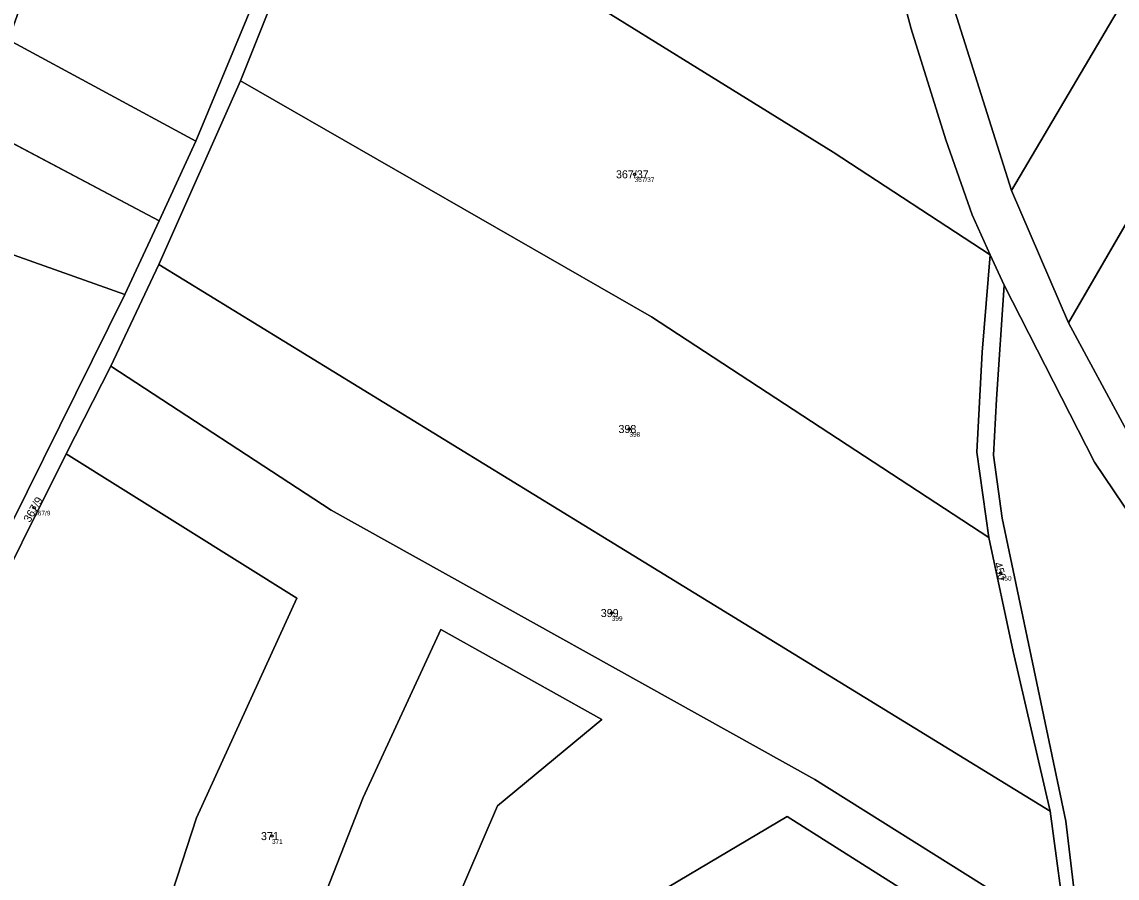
# Model space of a CAD drawing. Extents: x -700238 to -698499, y -1070626 to -1068006.
# Drawn here: x -699982.4 to -699749.9, y -1070051.8 to -1069869.9 of the extents above; entities that cross this region are included whole.
import ezdxf

# ---------------------------------------------------------------- set-up
doc = ezdxf.new("R2010")
doc.units = 0
for name, color, linetype in [('Definiční body', 7, 'Continuous'), ('Hranice parcel', 7, 'Continuous'), ('Parcelní čísla', 7, 'Continuous'), ('Polygon parcely', 7, 'Continuous')]:
    doc.layers.add(name, color=color, linetype=linetype)

msp = doc.modelspace()

# ---------------------------------------------------------------- linework, layer by layer
at = {"layer": 'Definiční body'}
for centre in [(-699852.34, -1069902.28994), (-699853.43, -1069956.39994), (-699979.84, -1069973.10994), (-699774.58, -1069986.95994), (-699857.19, -1069995.49994), (-699929.35, -1070042.87994)]:
    msp.add_circle(centre, 0.25, dxfattribs=at)
at = {"layer": 'Hranice parcel'}
for p, q in [((-699666.52, -1069772.25), (-699760.19, -1069933.83)), ((-699786.04, -1069862.19), (-699772.32, -1069905.7)), ((-699953.29, -1069912.16), (-700026.88, -1069873.22)), ((-699953.34, -1069921.42), (-699936.01, -1069882.46)), ((-699945.5, -1069895.24), (-699953.29, -1069912.16)), ((-699760.19, -1069933.83), (-699772.32, -1069905.7)), ((-699953.29, -1069912.16), (-699960.55, -1069927.82)), ((-699776.82, -1069919.37), (-699773.88, -1069925.87)), ((-699963.55, -1069943.05), (-699953.34, -1069921.42)), ((-699747.8, -1069956.79), (-699760.19, -1069933.83)), ((-699973.03, -1069961.64), (-699963.55, -1069943.05)), ((-699760.48, -1070064.46), (-699764.05, -1070037.6))]:
    msp.add_line(p, q, dxfattribs=at)
for points in [[(-699772.32, -1069905.7), (-699718.65, -1069814.76), (-699688.94, -1069762.18)], [(-699934.67, -1069766.79), (-699943.48, -1069779.63), (-699961.27, -1069826.27), (-699966.61, -1069825.7), (-699975.69, -1069846.7), (-699985.26, -1069873.71), (-699945.5, -1069895.24)], [(-699899.18, -1069805.87), (-699908.38, -1069815.7), (-699910.51, -1069819.6), (-699923.83, -1069843.06), (-699945.5, -1069895.24)], [(-699936.01, -1069882.46), (-699921.26, -1069845.41), (-699917.53, -1069838.96)], [(-699776.82, -1069919.37), (-699810.15, -1069897.58), (-699890.66, -1069847.63)], [(-699795.87, -1069862.82), (-699793.62, -1069871.36), (-699786.24, -1069895), (-699780.65, -1069910.87), (-699776.82, -1069919.37)], [(-699936.01, -1069882.46), (-699848.76, -1069932.55), (-699777.09, -1069979.45)], [(-699960.55, -1069927.82), (-700000.29, -1069913.75), (-700035.34, -1069906.98)], [(-699777.09, -1069979.45), (-699779.64, -1069961.35), (-699778.54, -1069940.11), (-699776.82, -1069919.37)], [(-699953.34, -1069921.42), (-699857.82, -1069980.05), (-699764.05, -1070037.6)], [(-699773.88, -1069925.87), (-699775.47, -1069950.06), (-699776.09, -1069961.97), (-699774.25, -1069975.35), (-699760.75, -1070039.69), (-699757.63, -1070065.88), (-699760.48, -1070064.46)], [(-699773.88, -1069925.87), (-699754.67, -1069963.44), (-699736.31, -1069990.62)], [(-699960.55, -1069927.82), (-699984.81, -1069976.77), (-700014.15, -1070035.06), (-700028.52, -1070073.11), (-700029.38, -1070092.64)], [(-699760.48, -1070064.46), (-699814.07, -1070030.89), (-699916.79, -1069973.61), (-699963.55, -1069943.05)], [(-700022.52, -1070128.11), (-700025.92, -1070097.31), (-700025.83, -1070074.31), (-700010.65, -1070036.99), (-699973.03, -1069961.64)], [(-699854.27, -1070196.19), (-699869.64, -1070194.62), (-699892.83, -1070188.84), (-699913.08, -1070162.82), (-699928.47, -1070131.78), (-699793.52, -1070055.46), (-699819.94, -1070038.73), (-699903.8, -1070088.48), (-699881.47, -1070036.48), (-699859.27, -1070018.12), (-699893.51, -1069998.97), (-699909.95, -1070034.69), (-699926.64, -1070077.05), (-699936.46, -1070111.92), (-699945.42, -1070093.75), (-699957.78, -1070077.02), (-699945.33, -1070038.99), (-699924.07, -1069992.37), (-699973.03, -1069961.64)], [(-699764.05, -1070037.6), (-699771.94, -1070003.65), (-699777.09, -1069979.45)]]:
    msp.add_lwpolyline(points, dxfattribs=at)
at = {"layer": 'Polygon parcely'}
for points in [[(-699666.31, -1070068.88), (-699678.79, -1070051.48), (-699693.87, -1070032.39), (-699718.55, -1069997.74), (-699733.13, -1069977.54), (-699747.8, -1069956.79), (-699760.19, -1069933.83), (-699772.32, -1069905.7), (-699786.04, -1069862.19), (-699789.84, -1069849.05), (-699797.44, -1069825.52), (-699807.14, -1069798.04), (-699808.65, -1069790.69), (-699809.76, -1069785.77), (-699810.32, -1069782.64), (-699811.1, -1069770), (-699809.25, -1069756.98), (-699803.18, -1069743.13), (-699792.05, -1069721.6), (-699779, -1069695.71)], [(-699820.65, -1069756.64), (-699822.8, -1069770.73), (-699819.03, -1069786.16), (-699815.5, -1069803.39), (-699809.91, -1069821.04), (-699795.87, -1069862.82), (-699793.62, -1069871.36), (-699786.24, -1069895), (-699780.65, -1069910.87), (-699776.82, -1069919.37), (-699773.88, -1069925.87), (-699754.67, -1069963.44), (-699736.31, -1069990.62), (-699727.1, -1070003.14), (-699698.54, -1070041.6), (-699662.16, -1070090.9)], [(-700025.83, -1070074.31), (-700010.65, -1070036.99), (-699973.03, -1069961.64), (-699963.55, -1069943.05), (-699953.34, -1069921.42), (-699936.01, -1069882.46), (-699921.26, -1069845.41), (-699917.53, -1069838.96), (-699918.26, -1069838.61), (-699908.41, -1069817.82), (-699905.55, -1069819.19), (-699899.18, -1069805.87), (-699908.38, -1069815.7), (-699910.51, -1069819.6), (-699923.83, -1069843.06), (-699945.5, -1069895.24), (-699953.29, -1069912.16), (-699960.55, -1069927.82), (-699984.81, -1069976.77), (-700014.15, -1070035.06), (-700028.52, -1070073.11)], [(-699723.72, -1070090.01), (-699733.66, -1070045.81), (-699736.31, -1069990.62), (-699754.67, -1069963.44), (-699773.88, -1069925.87), (-699775.47, -1069950.06), (-699776.09, -1069961.97), (-699774.25, -1069975.35), (-699760.75, -1070039.69), (-699757.63, -1070065.88)], [(-699760.48, -1070064.46), (-699814.07, -1070030.89), (-699916.79, -1069973.61), (-699963.55, -1069943.05), (-699973.03, -1069961.64), (-699924.07, -1069992.37), (-699945.33, -1070038.99), (-699957.78, -1070077.02)], [(-699957.78, -1070077.02), (-699945.33, -1070038.99), (-699924.07, -1069992.37), (-699973.03, -1069961.64), (-700010.65, -1070036.99), (-700025.83, -1070074.31)], [(-699793.52, -1070055.46), (-699819.94, -1070038.73), (-699903.8, -1070088.48), (-699881.47, -1070036.48), (-699859.27, -1070018.12), (-699893.51, -1069998.97), (-699909.95, -1070034.69), (-699926.64, -1070077.05)], [(-699926.64, -1070077.05), (-699909.95, -1070034.69), (-699893.51, -1069998.97), (-699859.27, -1070018.12), (-699881.47, -1070036.48), (-699903.8, -1070088.48), (-699819.94, -1070038.73), (-699793.52, -1070055.46)]]:
    msp.add_lwpolyline(points, dxfattribs=at)
for points in [[(-700026.88, -1069873.22), (-699953.29, -1069912.16), (-699945.5, -1069895.24), (-699985.26, -1069873.71), (-699975.69, -1069846.7), (-699966.61, -1069825.7), (-699961.27, -1069826.27), (-699943.48, -1069779.63), (-699934.67, -1069766.79), (-699980.93, -1069741.29), (-699999.19, -1069781.82), (-700020, -1069850.14)], [(-699718.65, -1069814.76), (-699688.94, -1069762.18), (-699710.07, -1069755.22), (-699786.04, -1069862.19), (-699772.32, -1069905.7)], [(-699772.32, -1069905.7), (-699760.19, -1069933.83), (-699666.52, -1069772.25), (-699688.94, -1069762.18), (-699718.65, -1069814.76)], [(-699985.26, -1069873.71), (-699945.5, -1069895.24), (-699923.83, -1069843.06), (-699910.51, -1069819.6), (-699908.38, -1069815.7), (-699899.18, -1069805.87), (-699891.37, -1069789.56), (-699915.87, -1069777), (-699934.67, -1069766.79), (-699943.48, -1069779.63), (-699961.27, -1069826.27), (-699966.61, -1069825.7), (-699975.69, -1069846.7)], [(-699666.52, -1069772.25), (-699760.19, -1069933.83), (-699747.8, -1069956.79), (-699670.62, -1069815.86), (-699648.85, -1069777.23)], [(-699795.87, -1069862.82), (-699877.25, -1069814.06), (-699887.28, -1069835.16), (-699886.33, -1069835.61), (-699887.34, -1069837.73), (-699886.21, -1069838.27), (-699890.66, -1069847.63), (-699810.15, -1069897.58), (-699776.82, -1069919.37), (-699780.65, -1069910.87), (-699786.24, -1069895), (-699793.62, -1069871.36)], [(-699890.66, -1069847.63), (-699892.24, -1069850.96), (-699897.84, -1069848.3), (-699901.7, -1069856.43), (-699915.43, -1069849.92), (-699911.57, -1069841.79), (-699917.53, -1069838.96), (-699921.26, -1069845.41), (-699936.01, -1069882.46), (-699848.76, -1069932.55), (-699777.09, -1069979.45), (-699779.64, -1069961.35), (-699778.54, -1069940.11), (-699776.82, -1069919.37), (-699810.15, -1069897.58)], [(-700026.88, -1069873.22), (-700031.54, -1069887.09), (-700035.34, -1069906.98), (-700000.29, -1069913.75), (-699960.55, -1069927.82), (-699953.29, -1069912.16)], [(-699953.34, -1069921.42), (-699857.82, -1069980.05), (-699764.05, -1070037.6), (-699771.94, -1070003.65), (-699777.09, -1069979.45), (-699848.76, -1069932.55), (-699936.01, -1069882.46)], [(-699960.55, -1069927.82), (-700000.29, -1069913.75), (-700035.34, -1069906.98), (-700040.48, -1069934.75), (-700041.71, -1069955.38), (-700048.46, -1069970.6), (-700048.21, -1069994.79), (-700039.13, -1070061.09), (-700032.26, -1070092.89), (-700029.38, -1070092.64), (-700028.52, -1070073.11), (-700014.15, -1070035.06), (-699984.81, -1069976.77)], [(-699776.82, -1069919.37), (-699778.54, -1069940.11), (-699779.64, -1069961.35), (-699777.09, -1069979.45), (-699771.94, -1070003.65), (-699764.05, -1070037.6), (-699760.48, -1070064.46), (-699757.63, -1070065.88), (-699760.75, -1070039.69), (-699774.25, -1069975.35), (-699776.09, -1069961.97), (-699775.47, -1069950.06), (-699773.88, -1069925.87)], [(-699764.05, -1070037.6), (-699857.82, -1069980.05), (-699953.34, -1069921.42), (-699963.55, -1069943.05), (-699916.79, -1069973.61), (-699814.07, -1070030.89), (-699760.48, -1070064.46)]]:
    msp.add_lwpolyline(points, close=True, dxfattribs=at)

# ---------------------------------------------------------------- texts
at = {"layer": 'Definiční body'}
for s, p in [('367/37', (-699852.34, -1069903.946)), ('398', (-699853.43, -1069958.056)), ('367/9', (-699979.84, -1069974.766)), ('450', (-699774.58, -1069988.616)), ('399', (-699857.19, -1069997.156)), ('371', (-699929.35, -1070044.536))]:
    msp.add_text(s, height=0.999996, dxfattribs=at).set_placement(p)
at = {"layer": 'Parcelní čísla'}
for s, p in [('367/37', (-699856.287, -1069903.14)), ('398', (-699855.755, -1069957.249)), ('399', (-699859.515, -1069996.35)), ('371', (-699931.675, -1070043.729))]:
    msp.add_text(s, height=1.699998, dxfattribs=at).set_placement(p)
for s, rotation, p in [('367/9', 59.9999972, (-699980.753, -1069976.391)), ('450', 286, (-699776.037, -1069984.959))]:
    msp.add_text(s, height=1.699998, rotation=rotation, dxfattribs=at).set_placement(p)

doc.saveas('drawing.dxf')
